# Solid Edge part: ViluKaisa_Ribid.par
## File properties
Username: kaisa
Author: kaisa
Template: Iso Metric Part.par
Last saved by: kaisa
Revision: 5
Application: Solid Edge
Accuracy: 0.990
Face Style: Model Default
Fill Style: Normal
Coef. of Thermal Exp: 0.0
Thermal Conductivity: 0.0
Specific Heat: 0.0
Modulus of Elasticity: 0.0
Poisson's Ratio: 0.0
Yield Stress: 0.0
Ultimate Stress: 0.0
Elongation: 0.0
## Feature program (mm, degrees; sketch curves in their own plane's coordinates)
swept protrusion "SweptProtrusion_4"
swept protrusion "SweptProtrusion_5"
swept protrusion "SweptProtrusion_6"
mirror "unnamed Mirror 1" of "SweptProtrusion_6", "SweptProtrusion_5" about plane through (0, 0, 0) normal (1, 0, 0)
swept protrusion "unnamed SweptProtrusion 1"
swept protrusion "unnamed SweptProtrusion 2"
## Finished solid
Body 1: solid body, 55 faces, 135 edges, 90 vertices, 5 separate solids.
  Faces by surface: spline 45, plane 10
  Edges by curve: line 70, spline 45, circle 20
Bounding box of the edges (mm; curved faces can reach further): 191.060 x 77.344 x 43.762, from (-95.5298, -77.3444, 6.2379) to (95.5298, 0, 50).
Planar faces by outward normal: +y 5, +z 5
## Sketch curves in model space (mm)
line (-87.3377, -39.2152, 50) -> (-84.4702, -35.1192, 50)
line (-84.4702, -35.1192, 50) -> (-92.6623, -29.3843, 50)
line (-92.6623, -29.3843, 50) -> (-95.5298, -33.4803, 50)
line (-95.5298, -33.4803, 50) -> (-87.3377, -39.2152, 50)
spline (-90, 0, 9.191) -> (-90, -16.5146, 22.1356) -> (-90, -35.4744, 53.6931)
arc centre (-88.3829, 0, 11.0099) radius 3.6329 from (-88.661, 0, 7.3877) through (-86.1012, 0, 8.1829) to (-84.7836, 0, 10.5172)
line (-84.7836, 0, 10.5172) -> (-84.5655, 0, 12.1101)
line (-84.5655, 0, 12.1101) -> (-94.5655, 0, 12.8778)
line (-94.5655, 0, 12.8778) -> (-94.7286, 0, 11.6864)
arc centre (-91.1545, 0, 11.1971) radius 3.6074 from (-94.7286, 0, 11.6864) through (-93.9616, 0, 8.9314) to (-91.4306, 0, 7.6003)
line (-91.4306, 0, 7.6003) -> (-88.661, 0, 7.3877)
line (5, -77.3444, 50) -> (5, -72.3444, 50)
line (5, -72.3444, 50) -> (-5, -72.3444, 50)
line (-5, -72.3444, 50) -> (-5, -77.3444, 50)
line (-5, -77.3444, 50) -> (5, -77.3444, 50)
line (-41.6273, -65.1806, 50) -> (-39.4099, -60.6992, 50)
line (-39.4099, -60.6992, 50) -> (-48.3727, -56.2644, 50)
line (-48.3727, -56.2644, 50) -> (-50.5901, -60.7458, 50)
line (-50.5901, -60.7458, 50) -> (-41.6273, -65.1806, 50)
spline (-45, 0, 9.7329) -> (-45, -31.0954, 16.5725) -> (-45, -60.7255, 50.0114)
arc centre (-41.9575, 0, 8.2279) radius 1.99 from (-39.9675, 0, 8.2279) through (-40.5918, 0, 6.7804) to (-41.9575, 0, 6.2379)
line (-39.9675, 0, 8.2279) -> (-39.9675, 0, 11.2379)
line (-39.9675, 0, 11.2379) -> (-49.9675, 0, 11.2379)
line (-49.9675, 0, 11.2379) -> (-49.9675, 0, 8.2279)
arc centre (-47.9775, 0, 8.2279) radius 1.99 from (-49.9675, 0, 8.2279) through (-49.3431, 0, 6.7804) to (-47.9775, 0, 6.2379)
line (-47.9775, 0, 6.2379) -> (-41.9575, 0, 6.2379)
spline (0, -75.0109, 50.7595) -> (0, -41.3161, 17.4069) -> (0, 0, 8.86)
line (0, 0, 54) -> (0, -80, 56.5662)
spline (-139.9105, 0, 54.0133) -> (-0.0002, 0, 56.5796) -> (139.9105, 0, 54.0133)
arc centre (3.0577, 0, 8.6835) radius 1.99 from (5.0477, 0, 8.6835) through (4.4233, 0, 7.2361) to (3.0577, 0, 6.6935)
line (5.0477, 0, 8.6835) -> (5.0477, 0, 11.6935)
line (5.0477, 0, 11.6935) -> (-4.9523, 0, 11.6935)
line (-4.9523, 0, 11.6935) -> (-4.9523, 0, 8.6835)
arc centre (-2.9623, 0, 8.6835) radius 1.99 from (-4.9523, 0, 8.6835) through (-4.328, 0, 7.2361) to (-2.9623, 0, 6.6935)
line (-2.9623, 0, 6.6935) -> (3.0577, 0, 6.6935)
spline (-114.8194, 0, 12.3978) -> (0, 0, 6.36) -> (114.8194, 0, 12.3978)
spline (139.9748, 0, 54) -> (129.3002, 0, 27.0039) -> (114.8194, 0, 12.3978)
spline (-139.9748, 0, 54) -> (0, 0, 56.5662) -> (139.9748, 0, 54)
spline (-139.9748, 0, 54) -> (-129.3002, 0, 27.0039) -> (-114.8194, 0, 12.3978)
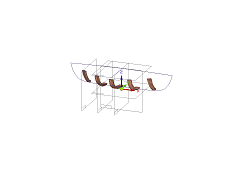
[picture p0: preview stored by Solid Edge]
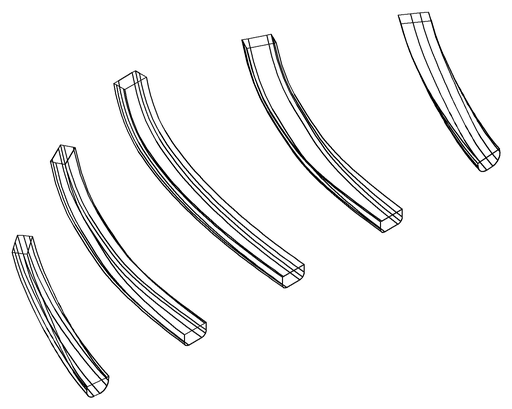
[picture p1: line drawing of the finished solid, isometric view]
